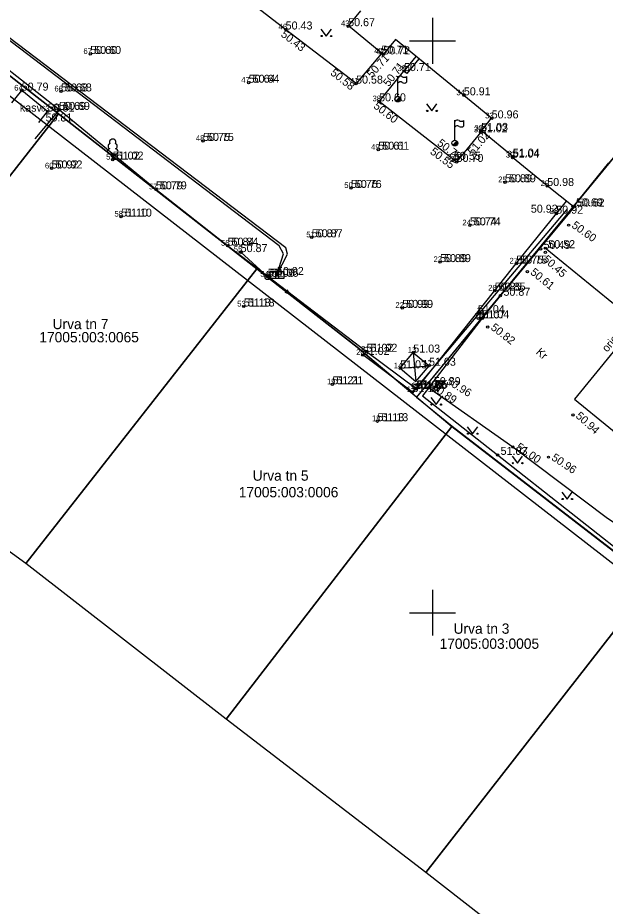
# Model space of a CAD drawing. Extents: x 640876 to 641418, y 6455595 to 6456085.
# Drawn here: x 641063.8 to 641115.1, y 6455774.3 to 6455852 of the extents above; entities that cross this region are included whole.
import ezdxf

# ---------------------------------------------------------------- set-up
doc = ezdxf.new("R2010")
doc.units = 0
for name, color, linetype in [('AED', 7, 'Continuous'), ('HALJASTUS', 7, 'Continuous'), ('HOONE', 7, 'Continuous'), ('HOONEDET', 7, 'Continuous'), ('KORGUS', 7, 'Continuous'), ('MOOTKORG', 7, 'Continuous'), ('MOOTMPUNKT', 7, 'Continuous'), ('MOOTNR', 7, 'Continuous'), ('MOOTPIIR', 7, 'Continuous'), ('MPKAABEL', 7, 'Continuous'), ('MPOHULIIN', 7, 'Continuous'), ('PIIR', 7, 'Continuous'), ('POST', 7, 'Continuous'), ('PUU', 7, 'Continuous'), ('RAJATIS', 7, 'Continuous'), ('TEE', 7, 'Continuous'), ('VORK', 7, 'Continuous'), ('VTRASS', 7, 'Continuous')]:
    doc.layers.add(name, color=color, linetype=linetype)

msp = doc.modelspace()

# ---------------------------------------------------------------- linework, layer by layer
at = {"layer": 'AED'}
for points in [[(641098.569, 6455819.563), (641094.24, 6455822.817), (641082.103, 6455832.091), (641075.84, 6455837.015), (641067.377, 6455843.962), (641058.994, 6455850.552)], [(641067.377, 6455843.962), (641065.272, 6455841.425)], [(641099.859, 6455819.896), (641104.367, 6455825.748), (641105.944, 6455827.712), (641112.44, 6455835.512)], [(641099.859, 6455819.896), (641099.12, 6455818.953), (641105.695, 6455813.799), (641118.57, 6455803.662), (641126.581, 6455797.35), (641134.461, 6455791.227), (641139.651, 6455787.174)]]:
    msp.add_lwpolyline(points, dxfattribs=at)
at = {"layer": 'HALJASTUS'}
for p, q in [((641090.259, 6455851.031), (641090.722, 6455850.424)), ((641090.722, 6455850.424), (641091.168, 6455851.031)), ((641099.485, 6455844.482), (641099.948, 6455843.875)), ((641099.948, 6455843.875), (641100.394, 6455844.482)), ((641099.857, 6455818.804), (641100.321, 6455818.198)), ((641100.321, 6455818.198), (641100.766, 6455818.804)), ((641103.045, 6455816.258), (641103.509, 6455815.651)), ((641103.509, 6455815.651), (641103.954, 6455816.258)), ((641106.963, 6455813.685), (641107.427, 6455813.079)), ((641107.427, 6455813.079), (641107.872, 6455813.685)), ((641111.308, 6455810.548), (641111.772, 6455809.941)), ((641111.772, 6455809.941), (641112.217, 6455810.548))]:
    msp.add_line(p, q, dxfattribs=at)
for centre in [(641090.321, 6455850.424), (641091.15, 6455850.424), (641099.547, 6455843.875), (641100.376, 6455843.875), (641099.92, 6455818.198), (641100.748, 6455818.198), (641103.108, 6455815.651), (641103.936, 6455815.651), (641107.025, 6455813.079), (641107.854, 6455813.079), (641111.371, 6455809.941), (641112.2, 6455809.941)]:
    msp.add_circle(centre, 0.055, dxfattribs=at)
at = {"layer": 'HOONE'}
for points in [[(641115.375, 6455839.33), (641112.285, 6455835.53), (641110.028, 6455837.31), (641106.997, 6455839.791), (641107.057, 6455839.863), (641104.273, 6455842.142), (641105.165, 6455843.231), (641096.764, 6455850.107), (641095.705, 6455848.813), (641092.657, 6455851.308), (641093.744, 6455852.636)], [(641097.178, 6455821.369), (641098.327, 6455822.745)], [(641098.327, 6455822.745), (641099.702, 6455821.595)], [(641097.178, 6455821.369), (641098.553, 6455820.219)], [(641098.553, 6455820.219), (641099.702, 6455821.595)]]:
    msp.add_lwpolyline(points, dxfattribs=at)
at = {"layer": 'HOONEDET'}
msp.add_line((641098.561, 6455848.637), (641097.514, 6455847.358), dxfattribs=at)
for points in [[(641098.808, 6455848.434), (641097.762, 6455847.156), (641097.514, 6455847.358)], [(641098.327, 6455822.745), (641098.553, 6455820.219)], [(641097.178, 6455821.369), (641099.702, 6455821.595)]]:
    msp.add_lwpolyline(points, dxfattribs=at)
at = {"layer": 'KORGUS'}
for centre in [(641087.174, 6455850.994), (641070.103, 6455848.854), (641095.54, 6455848.884), (641097.514, 6455847.358), (641083.942, 6455846.338), (641093.329, 6455846.264), (641067.544, 6455845.576), (641095.339, 6455844.712), (641066.379, 6455843.822), (641067.377, 6455843.962), (641104.221, 6455842.006), (641079.954, 6455841.251), (641095.269, 6455840.481), (641072.06, 6455839.619), (641101.878, 6455839.599), (641066.72, 6455838.843), (641102.107, 6455839.413), (641092.872, 6455837.138), (641106.342, 6455837.636), (641075.84, 6455837.015), (641110.821, 6455834.887), (641072.792, 6455834.632), (641103.268, 6455833.864), (641111.893, 6455833.884), (641089.452, 6455832.824), (641082.103, 6455832.091), (641109.87, 6455831.518), (641100.666, 6455830.655), (641107.329, 6455830.526), (641085.608, 6455829.372), (641108.292, 6455829.826), (641105.441, 6455828.163), (641083.517, 6455826.773), (641097.364, 6455826.653), (641104.826, 6455824.979), (641094.24, 6455822.817), (641100.938, 6455820.207), (641091.255, 6455819.97), (641098.569, 6455819.563), (641098.66, 6455819.632), (641099.665, 6455819.667), (641112.27, 6455817.296), (641095.192, 6455816.745), (641107.025, 6455814.477), (641110.138, 6455813.6)]:
    msp.add_circle(centre, 0.1, dxfattribs=at)
at = {"layer": 'MOOTMPUNKT'}
for centre in [(641092.635, 6455851.282), (641087.174, 6455850.994), (641070.103, 6455848.854), (641095.54, 6455848.884), (641095.705, 6455848.813), (641097.514, 6455847.358), (641083.942, 6455846.338), (641093.329, 6455846.264), (641064.11, 6455845.65), (641067.544, 6455845.576), (641102.742, 6455845.239), (641095.339, 6455844.712), (641066.379, 6455843.822), (641067.369, 6455843.962), (641067.377, 6455843.962), (641105.177, 6455843.221), (641104.221, 6455842.006), (641104.26, 6455842.126), (641079.954, 6455841.251), (641095.269, 6455840.481), (641072.06, 6455839.619), (641101.878, 6455839.599), (641106.997, 6455839.791), (641107.033, 6455839.883), (641066.72, 6455838.843), (641102.107, 6455839.413), (641092.872, 6455837.138), (641106.342, 6455837.636), (641110.028, 6455837.31), (641075.84, 6455837.015), (641110.821, 6455834.887), (641112.285, 6455835.53), (641112.44, 6455835.512), (641072.792, 6455834.632), (641103.268, 6455833.864), (641089.452, 6455832.824), (641082.103, 6455832.091), (641109.451, 6455831.813), (641109.861, 6455831.873), (641083.244, 6455831.53), (641100.666, 6455830.655), (641107.329, 6455830.526), (641085.608, 6455829.372), (641086.415, 6455829.528), (641105.441, 6455828.163), (641105.944, 6455827.712), (641083.517, 6455826.773), (641097.364, 6455826.653), (641103.971, 6455826.189), (641104.018, 6455825.726), (641104.367, 6455825.748), (641093.912, 6455822.539), (641094.24, 6455822.817), (641098.327, 6455822.745), (641099.702, 6455821.595), (641097.178, 6455821.369), (641091.255, 6455819.97), (641098.259, 6455819.294), (641098.569, 6455819.563), (641098.66, 6455819.632), (641099.859, 6455819.896), (641095.192, 6455816.745), (641105.695, 6455813.799)]:
    msp.add_circle(centre, 0.1, dxfattribs=at)
at = {"layer": 'MOOTPIIR'}
msp.add_lwpolyline([(641060.916, 6455895.936), (641100.061, 6455950.482), (641099.586, 6455952.159), (641069.132, 6455984.035), (641066.132, 6455988.623), (641076.463, 6456005.049), (641230.642, 6456010.048), (641237.36, 6455995.24), (641237.24, 6455992.81), (641236.258, 6455990.888), (641229.041, 6455971.315), (641203.026, 6455909.57), (641225.257, 6455906.847), (641239.512, 6455898.491), (641200.195, 6455851.697), (641192.016, 6455859.099), (641169.785, 6455829.138), (641192.025, 6455807.568), (641252.96, 6455758.075), (641231.388, 6455736.74), (641191.474, 6455775.975), (641152.419, 6455787.914), (641136.351, 6455788.307), (641049.066, 6455856.043)], dxfattribs=at)
at = {"layer": 'MPKAABEL'}
for points in [[(641086.415, 6455829.528), (641086.973, 6455831.373), (641086.62, 6455832.079), (641057.431, 6455854.322), (641053.1, 6455857.47), (641049.11, 6455860.51), (641045.12, 6455863.55), (641041.795, 6455865.56)], [(641086.415, 6455829.528), (641087.321, 6455831.352), (641087.203, 6455831.916), (641057.525, 6455854.457), (641053.15, 6455857.64), (641049.7, 6455860.36), (641046.25, 6455863.08), (641042.44, 6455865.41)]]:
    msp.add_lwpolyline(points, dxfattribs=at)
at = {"layer": 'MPOHULIIN'}
for p, q in [((641085.608, 6455829.372), (641085.608, 6455829.372)), ((641085.805, 6455829.217), (641087.574, 6455827.827)), ((641087.574, 6455827.827), (641087.127, 6455827.989)), ((641087.574, 6455827.827), (641087.312, 6455828.224))]:
    msp.add_line(p, q, dxfattribs=at)
at = {"layer": 'PIIR'}
for points in [[(641098.62, 6455818.85), (641093.41, 6455823.22), (641084.65, 6455830.08), (641067.32, 6455843.61), (641055.55, 6455852.8), (641061.31, 6455859.9), (641051.68, 6455867.61), (641067, 6455888.54), (641060.97, 6455894.57), (641075.14, 6455914.24), (641087.11, 6455930.82), (641102.26, 6455951.82), (641160.91, 6455891.99), (641157.02, 6455885.66), (641139.49, 6455869), (641124.05, 6455849.81)], [(641216.67, 6455752.61), (641192, 6455776.86), (641152.58, 6455788.91), (641136.9, 6455789.33), (641119.28, 6455802.72), (641101.72, 6455816.27), (641098.61, 6455818.83), (641124.03, 6455849.78), (641139.51, 6455868.99), (641157, 6455885.69), (641191.84, 6455860.59), (641168.46, 6455829.03), (641191.37, 6455806.79), (641234.69, 6455771.62)], [(641029.34, 6455830.8), (641049.71, 6455856.81), (641055.55, 6455852.8), (641067.32, 6455843.61), (641046.64, 6455817.21)], [(641067.32, 6455843.61), (641084.65, 6455830.08), (641064.46, 6455804.29), (641046.64, 6455817.21)], [(641101.69, 6455816.28), (641081.98, 6455790.7), (641064.46, 6455804.29), (641084.65, 6455830.08), (641093.41, 6455823.22)], [(641099.43, 6455777.27), (641081.98, 6455790.7), (641101.69, 6455816.28), (641119.25, 6455802.74)], [(641129.48, 6455779.84), (641138.9, 6455768.3), (641127.85, 6455755.11), (641099.43, 6455777.27), (641119.25, 6455802.74), (641136.89, 6455789.31)]]:
    msp.add_lwpolyline(points, close=True, dxfattribs=at)
at = {"layer": 'POST'}
for p, q in [((641086.279, 6455829.827), (641086.279, 6455829.23)), ((641086.551, 6455829.827), (641086.551, 6455829.23))]:
    msp.add_line(p, q, dxfattribs=at)
msp.add_lwpolyline([(641083.244, 6455831.53), (641085.608, 6455829.372)], dxfattribs=at)
msp.add_lwpolyline([(641085.818, 6455829.827), (641087.012, 6455829.827), (641087.012, 6455829.23), (641085.818, 6455829.23)], close=True, dxfattribs=at)
for centre, radius in [((641083.244, 6455831.53), 0.125), ((641083.244, 6455831.53), 0.105), ((641083.244, 6455831.53), 0.0851), ((641083.244, 6455831.53), 0.0651), ((641083.244, 6455831.53), 0.0451), ((641083.244, 6455831.53), 0.0251), ((641083.244, 6455831.53), 0.00511), ((641085.608, 6455829.372), 0.25)]:
    msp.add_circle(centre, radius, dxfattribs=at)
at = {"layer": 'PUU'}
for p, q in [((641072.3, 6455840.094), (641071.82, 6455840.094)), ((641072.06, 6455839.619), (641072.06, 6455840.094)), ((641072.44, 6455839.619), (641072.06, 6455839.619))]:
    msp.add_line(p, q, dxfattribs=at)
msp.add_lwpolyline([(641111.73, 6455835.265), (641098.259, 6455819.294), (641093.912, 6455822.539)], dxfattribs=at)
for centre, radius, start, end in [((641072.06, 6455841.139), 0.277, 332.5799, 207.4201), ((641071.823, 6455840.332), 0.238, 90.0016, 269.3953), ((641071.89, 6455840.792), 0.233, 109.02174, 253.14154), ((641072.231, 6455840.792), 0.233, 286.85082, 70.98591), ((641072.298, 6455840.332), 0.238, 270.6047, 89.9984)]:
    msp.add_arc(centre, radius, start, end, dxfattribs=at)
at = {"layer": 'RAJATIS'}
for p, q in [((641096.974, 6455845.156), (641096.974, 6455846.906)), ((641097.727, 6455846.875), (641097.727, 6455846.375)), ((641063.257, 6455844.591), (641064.11, 6455845.65)), ((641096.797, 6455844.73), (641097.151, 6455845.083)), ((641096.974, 6455844.906), (641096.974, 6455844.906)), ((641065.597, 6455842.852), (641066.379, 6455843.822)), ((641101.954, 6455841.314), (641101.954, 6455843.064)), ((641102.706, 6455843.033), (641102.706, 6455842.533)), ((641101.776, 6455840.888), (641102.13, 6455841.241)), ((641101.954, 6455841.064), (641101.954, 6455841.064))]:
    msp.add_line(p, q, dxfattribs=at)
msp.add_lwpolyline([(641066.379, 6455843.822), (641064.11, 6455845.65)], dxfattribs=at)
for centre in [(641096.974, 6455844.906), (641101.954, 6455841.064)]:
    msp.add_circle(centre, 0.25, dxfattribs=at)
for centre, radius, start, end in [((641097.197, 6455846.622), 0.288, 57.89407, 140.73656), ((641097.531, 6455847.155), 0.341, 237.89407, 305.02189), ((641097.197, 6455846.122), 0.288, 57.89407, 140.73656), ((641097.531, 6455846.655), 0.341, 237.89407, 305.02189), ((641096.974, 6455844.906), 0.225, 224.85406, 45.03563), ((641096.974, 6455844.906), 0.2, 224.84272, 45.04698), ((641096.974, 6455844.906), 0.175, 224.82813, 45.06157), ((641096.974, 6455844.906), 0.15, 224.80867, 45.08103), ((641096.974, 6455844.906), 0.125, 224.78144, 45.10826), ((641096.974, 6455844.906), 0.1, 224.74058, 45.14911), ((641096.974, 6455844.906), 0.075, 224.67249, 45.2172), ((641096.974, 6455844.906), 0.05, 224.53632, 45.35338), ((641096.974, 6455844.906), 0.025, 224.12776, 45.76193), ((641102.176, 6455842.78), 0.288, 57.89407, 140.73656), ((641102.511, 6455843.313), 0.341, 237.89407, 305.02189), ((641102.176, 6455842.28), 0.288, 57.89407, 140.73656), ((641102.511, 6455842.813), 0.341, 237.89407, 305.02189), ((641101.954, 6455841.064), 0.225, 224.85406, 45.03563), ((641101.954, 6455841.064), 0.2, 224.84272, 45.04698), ((641101.954, 6455841.064), 0.175, 224.82813, 45.06157), ((641101.954, 6455841.064), 0.15, 224.80867, 45.08103), ((641101.954, 6455841.064), 0.125, 224.78144, 45.10826), ((641101.954, 6455841.064), 0.1, 224.74058, 45.14911), ((641101.954, 6455841.064), 0.075, 224.67249, 45.2172), ((641101.954, 6455841.064), 0.05, 224.53632, 45.35338), ((641101.954, 6455841.064), 0.025, 224.12776, 45.76193)]:
    msp.add_arc(centre, radius, start, end, dxfattribs=at)
at = {"layer": 'TEE'}
for points in [[(641095.54, 6455848.884), (641093.329, 6455846.264), (641087.174, 6455850.994), (641077.361, 6455858.57), (641074.828, 6455860.587), (641075.266, 6455863.793)], [(641104.221, 6455842.006), (641102.107, 6455839.413), (641101.878, 6455839.599), (641095.339, 6455844.712), (641097.514, 6455847.358)], [(641098.66, 6455819.632), (641105.441, 6455828.163), (641107.329, 6455830.526), (641111.703, 6455835.989)], [(641138.34, 6455800.592), (641134.265, 6455803.889), (641135.895, 6455805.73), (641133.001, 6455808.025), (641131.761, 6455809.021), (641133.931, 6455811.803), (641128.658, 6455815.989), (641118.513, 6455824.816), (641109.861, 6455831.873)], [(641146.099, 6455786.99), (641144.934, 6455788.318), (641140.92, 6455790.807), (641133.213, 6455794.381), (641127.043, 6455799.198), (641121.299, 6455804.336), (641115.306, 6455808.241), (641107.025, 6455814.477), (641099.665, 6455819.667)]]:
    msp.add_lwpolyline(points, dxfattribs=at)
at = {"layer": 'VORK'}
for p, q in [((641100, 6455852), (641100, 6455848)), ((641098, 6455850), (641102, 6455850)), ((641100, 6455802), (641100, 6455798)), ((641098, 6455800), (641102, 6455800))]:
    msp.add_line(p, q, dxfattribs=at)
at = {"layer": 'VTRASS'}
msp.add_lwpolyline([(641123.713, 6455832.522), (641112.411, 6455818.681), (641151.409, 6455786.838)], dxfattribs=at)

# ---------------------------------------------------------------- texts
at = {"layer": 'KORGUS'}
for s, rotation, p in [('50.43', 322.38888, (641086.702, 6455850.449)), ('50.71', 47.86126, (641094.715, 6455846.713)), ('50.58', 321.75114, (641091.024, 6455847.092)), ('50.71', 52.44568, (641096.179, 6455845.943)), ('50.60', 322.15438, (641094.794, 6455844.182)), ('51.02', 48.9733, (641103.535, 6455839.949)), ('50.70', 322.83843, (641100.358, 6455840.93)), ('50.55', 323.0682, (641099.737, 6455840.182)), (' 50.60', 324.45994, (641111.893, 6455833.884)), (' 50.45', 318.00972, (641109.402, 6455830.998)), (' 50.61', 320.85417, (641108.292, 6455829.826)), (' 50.82', 322.37645, (641104.826, 6455824.979)), (' 50.96', 328.28652, (641100.938, 6455820.207)), (' 50.89', 326.634, (641099.665, 6455819.667)), (' 50.94', 318.03277, (641112.27, 6455817.296)), (' 51.00', 325.98001, (641107.025, 6455814.477)), (' 50.96', 326.38902, (641110.121, 6455813.545))]:
    msp.add_text(s, height=0.7, rotation=rotation, dxfattribs=at).set_placement(p)
for s, p in [('50.60', (641070.453, 6455848.854)), ('50.64', (641084.292, 6455846.338)), ('50.68', (641067.894, 6455845.576)), ('50.69', (641067.727, 6455843.962)), ('50.81', (641066.191, 6455842.952)), ('50.75', (641080.304, 6455841.251)), ('50.61', (641095.619, 6455840.481)), ('51.02', (641072.41, 6455839.619)), ('50.92', (641067.07, 6455838.843)), ('50.89', (641106.692, 6455837.636)), ('50.79', (641076.19, 6455837.015)), ('50.76', (641093.222, 6455837.138)), ('50.92', (641108.596, 6455834.976)), ('51.10', (641073.142, 6455834.632)), ('50.74', (641103.618, 6455833.864)), ('50.87', (641089.802, 6455832.824)), ('50.84', (641082.453, 6455832.091)), ('50.89', (641101.016, 6455830.655)), ('50.75', (641107.679, 6455830.526)), ('51.06', (641085.958, 6455829.372)), ('50.85', (641105.791, 6455828.163)), ('51.18', (641083.867, 6455826.773)), ('50.99', (641097.714, 6455826.653)), ('51.02', (641094.59, 6455822.817)), ('51.21', (641091.605, 6455819.97)), ('51.05', (641098.919, 6455819.563)), ('51.05', (641099.01, 6455819.632)), ('51.13', (641095.542, 6455816.745))]:
    msp.add_text(s, height=0.7, dxfattribs=at).set_placement(p)
at = {"layer": 'MOOTKORG'}
for s, p in [('50.67', (641092.635, 6455851.282)), ('50.43', (641087.174, 6455850.994)), ('50.60', (641070.103, 6455848.854)), ('50.71', (641095.54, 6455848.884)), ('50.72', (641095.705, 6455848.813)), ('50.71', (641097.514, 6455847.358)), ('50.64', (641083.942, 6455846.338)), ('50.58', (641093.329, 6455846.264)), ('50.79', (641064.11, 6455845.65)), ('50.68', (641067.544, 6455845.576)), ('50.91', (641102.742, 6455845.239)), ('50.60', (641095.339, 6455844.712)), ('50.81', (641066.379, 6455843.822)), ('50.69', (641067.369, 6455843.962)), ('50.69', (641067.377, 6455843.962)), ('50.96', (641105.177, 6455843.221)), ('51.02', (641104.221, 6455842.006)), ('51.03', (641104.26, 6455842.126)), ('50.75', (641079.954, 6455841.251)), ('50.61', (641095.269, 6455840.481)), ('51.02', (641072.06, 6455839.619)), ('51.04', (641106.997, 6455839.791)), ('51.04', (641107.033, 6455839.883)), ('50.92', (641066.72, 6455838.843)), ('50.55', (641101.878, 6455839.599)), ('50.70', (641102.107, 6455839.413)), ('50.89', (641106.342, 6455837.636)), ('50.98', (641110.028, 6455837.31)), ('50.79', (641075.84, 6455837.015)), ('50.76', (641092.872, 6455837.138)), (' 50.69', (641112.285, 6455835.53)), (' 50.62', (641112.44, 6455835.512)), ('51.10', (641072.792, 6455834.632)), ('50.92', (641110.821, 6455834.887)), ('50.74', (641103.268, 6455833.864)), ('50.87', (641089.452, 6455832.824)), ('50.84', (641082.103, 6455832.091)), (' 50.52', (641109.861, 6455831.873)), ('50.87', (641083.244, 6455831.53)), (' 50.49', (641109.451, 6455831.813)), ('50.89', (641100.666, 6455830.655)), ('50.75', (641107.329, 6455830.526)), ('50.92', (641086.415, 6455829.528)), ('51.06', (641085.608, 6455829.372)), ('50.85', (641105.441, 6455828.163)), (' 50.87', (641105.944, 6455827.712)), ('51.18', (641083.517, 6455826.773)), ('50.99', (641097.364, 6455826.653)), ('51.04', (641103.971, 6455826.189)), ('51.07', (641104.018, 6455825.726)), ('51.04', (641104.367, 6455825.748)), ('51.02', (641093.912, 6455822.539)), ('51.02', (641094.24, 6455822.817)), ('51.03', (641098.327, 6455822.745)), ('51.03', (641097.178, 6455821.369)), ('51.03', (641099.702, 6455821.595)), ('51.21', (641091.255, 6455819.97)), ('51.05', (641098.569, 6455819.563)), ('51.05', (641098.66, 6455819.632)), (' 50.89', (641099.859, 6455819.896)), ('51.14', (641098.259, 6455819.294)), ('51.13', (641095.192, 6455816.745)), (' 51.03', (641105.695, 6455813.799))]:
    msp.add_text(s, height=0.7, dxfattribs=at).set_placement(p)
at = {"layer": 'MOOTNR'}
for s, p in [('46', (641086.549, 6455850.994)), ('43', (641092.01, 6455851.282)), ('67', (641069.503, 6455848.854)), ('40', (641094.915, 6455848.884)), ('42', (641095.055, 6455848.813)), ('39', (641096.939, 6455847.358)), ('47', (641083.292, 6455846.338)), ('41', (641092.804, 6455846.264)), ('64', (641063.46, 6455845.65)), ('66', (641066.969, 6455845.576)), ('38', (641094.764, 6455844.712)), ('34', (641102.092, 6455845.239)), ('63', (641065.804, 6455843.822)), ('62', (641066.777, 6455843.962)), ('61', (641066.894, 6455843.962)), ('33', (641104.602, 6455843.221)), ('35', (641103.621, 6455842.006)), ('32', (641103.66, 6455842.126)), ('48', (641079.329, 6455841.251)), ('49', (641094.644, 6455840.481)), ('31', (641106.558, 6455839.883)), ('59', (641071.485, 6455839.619)), ('37', (641101.278, 6455839.599)), ('36', (641101.532, 6455839.413)), ('30', (641106.422, 6455839.791)), ('60', (641066.145, 6455838.843)), ('25', (641105.742, 6455837.636)), ('57', (641075.24, 6455837.015)), ('50', (641092.297, 6455837.138)), ('29', (641109.453, 6455837.31)), ('58', (641072.217, 6455834.632)), ('28', (641110.246, 6455834.887)), ('24', (641102.618, 6455833.864)), ('51', (641088.977, 6455832.824)), ('56', (641081.528, 6455832.091)), ('55', (641082.644, 6455831.53)), ('23', (641100.091, 6455830.655)), ('27', (641106.729, 6455830.526)), ('54', (641084.959, 6455829.372)), ('52', (641085.815, 6455829.528)), ('26', (641104.866, 6455828.163)), ('53', (641082.943, 6455826.773)), ('22', (641096.764, 6455826.653)), ('1', (641103.846, 6455826.189)), ('11', (641103.643, 6455825.726)), ('10', (641103.892, 6455825.748)), ('21', (641093.765, 6455822.817)), ('13', (641097.852, 6455822.745)), ('20', (641093.337, 6455822.539)), ('14', (641096.628, 6455821.369)), ('12', (641099.202, 6455821.595)), ('19', (641090.78, 6455819.97)), ('16', (641098.185, 6455819.632)), ('17', (641097.759, 6455819.294)), ('15', (641098.069, 6455819.563)), ('18', (641094.717, 6455816.745))]:
    msp.add_text(s, height=0.5, dxfattribs=at).set_placement(p)
at = {"layer": 'PIIR'}
for s, p in [('Urva tn 7', (641066.81, 6455824.794)), ('17005:003:0065', (641065.65, 6455823.64)), ('Urva tn 5', (641084.294, 6455811.539)), ('17005:003:0006', (641083.08, 6455810.09)), ('Urva tn 3', (641101.844, 6455798.158))]:
    msp.add_text(s, height=0.9, dxfattribs=at).set_placement(p)
msp.add_text('17005:003:0005', height=0.9, rotation=360, dxfattribs=at).set_placement((641100.62, 6455796.84))
at = {"layer": 'RAJATIS'}
msp.add_text('kasv', height=0.7, dxfattribs=at).set_placement((641063.948, 6455843.81))
at = {"layer": 'TEE'}
msp.add_text('Kr', height=0.7, rotation=317.8346, dxfattribs=at).set_placement((641108.996, 6455822.709))
at = {"layer": 'VTRASS'}
msp.add_text('orient', height=0.7, rotation=49.83469, dxfattribs=at).set_placement((641115.273, 6455822.732))

doc.saveas('drawing.dxf')
